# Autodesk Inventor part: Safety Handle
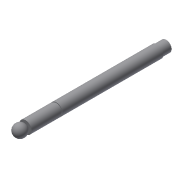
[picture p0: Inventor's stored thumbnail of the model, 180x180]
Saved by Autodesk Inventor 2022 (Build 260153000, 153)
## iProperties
Created: 2002-02
Part Number: Safety Handle
Document SubType Name: Modeling
Designer: ***
Density: 1 g/cm^3
Material: Generic
Mass: 54.3914 g
Surface Area: 130.219 cm^2
Volume: 54.3914 cm^3
Appearance: Default
Control State: 0
Master: False
Checked Out: False
Shininess: 77.0
Length Units: 11269
Angle Units: 11279
Time Units: 11290
Mass Units: 11283
Length Display Precision: 3
Angle Display Precision: 2
Density: 0.0
Volumn: 0.0
Area: 0.0
PropertySet Name: Model Information
Author: ***
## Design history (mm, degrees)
sketch "Sketch1"
  geometry: L1 (0, 205)-(8, 205); L2 (8, 205)-(8, 192); L3 (8, 192)-(9, 192); L4 (9, 192)-(9, 45); L5 (9, 45)-(8, 45); L6 (8, 45)-(8, 43); L7 (8, 43)-(9, 43); L8 (9, 43)-(9, 0); L9 (9, 0)-(0, 0); L10 (0, 0)-(0, 205)
  constraints: 20 end point, 7 parallel, 1 collinear, 1 horizontal, 1 perpendicular
  dimensions: "d0" = 13 distance of L1.end L2.end; "d1" = 2 distance of L4.end L7.end; "d2" = 43 distance of L7.end L8.end; "d3" = 205 distance of L9.end L1.start; "d4" = 16 diameter of L2 L10; "d5" = 18 diameter of L4 L10; "d6" = 16 diameter of L6.end L10
revolve "Revolution1" sketch "Sketch1" stored, may be unused: angle "d7" = 90 deg
sketch "Sketch2"
  geometry: L1 (0, 1)-(0, -17); L2 (-9, 0)-(9, 0) reference; A1 r 9 centre (0, -8) between (0, -17) and (0, 1)
  constraints: 2 end point, 2 point on circle, 1 centre point, 1 midpoint, 1 vertical
  dimensions: "d8" = 9 radius of A1; "d9" = 1 distance from line of L2 L1.start
revolve "Revolution2" sketch "Sketch2" stored, may be unused: angle "d10" = 90 deg
body "Solid1"
